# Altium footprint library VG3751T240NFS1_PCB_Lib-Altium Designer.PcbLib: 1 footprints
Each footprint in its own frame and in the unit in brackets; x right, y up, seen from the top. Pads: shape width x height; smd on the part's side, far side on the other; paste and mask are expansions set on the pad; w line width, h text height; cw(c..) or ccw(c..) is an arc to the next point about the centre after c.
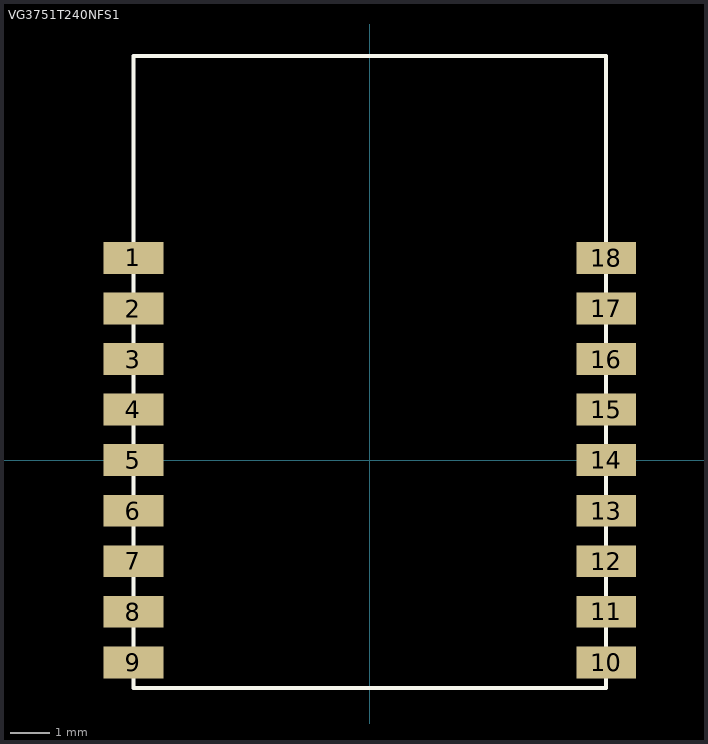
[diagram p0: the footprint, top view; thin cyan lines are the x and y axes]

## VG3751T240NFS1 [mm]
pads (19):
  round 1 on Top Overlay: 1(-6.985,6.35)
  rect 1.5x0.8 smd: 1(-5.94,5.08) 2(-5.94,3.81) 3(-5.94,2.54) 4(-5.94,1.27) 5(-5.94,0) 6(-5.94,-1.27) 7(-5.94,-2.54) 8(-5.94,-3.81) 9(-5.94,-5.08) 10(5.94,-5.08) 11(5.94,-3.81) 12(5.94,-2.54) 13(5.94,-1.27) 14(5.94,0) 15(5.94,1.27) 16(5.94,2.54) 17(5.94,3.81) 18(5.94,5.08)
Top Overlay:
  lines w0.1: -5.94,-5.72 5.94,-5.72 5.94,10.16 -5.94,10.16 -5.94,-5.72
